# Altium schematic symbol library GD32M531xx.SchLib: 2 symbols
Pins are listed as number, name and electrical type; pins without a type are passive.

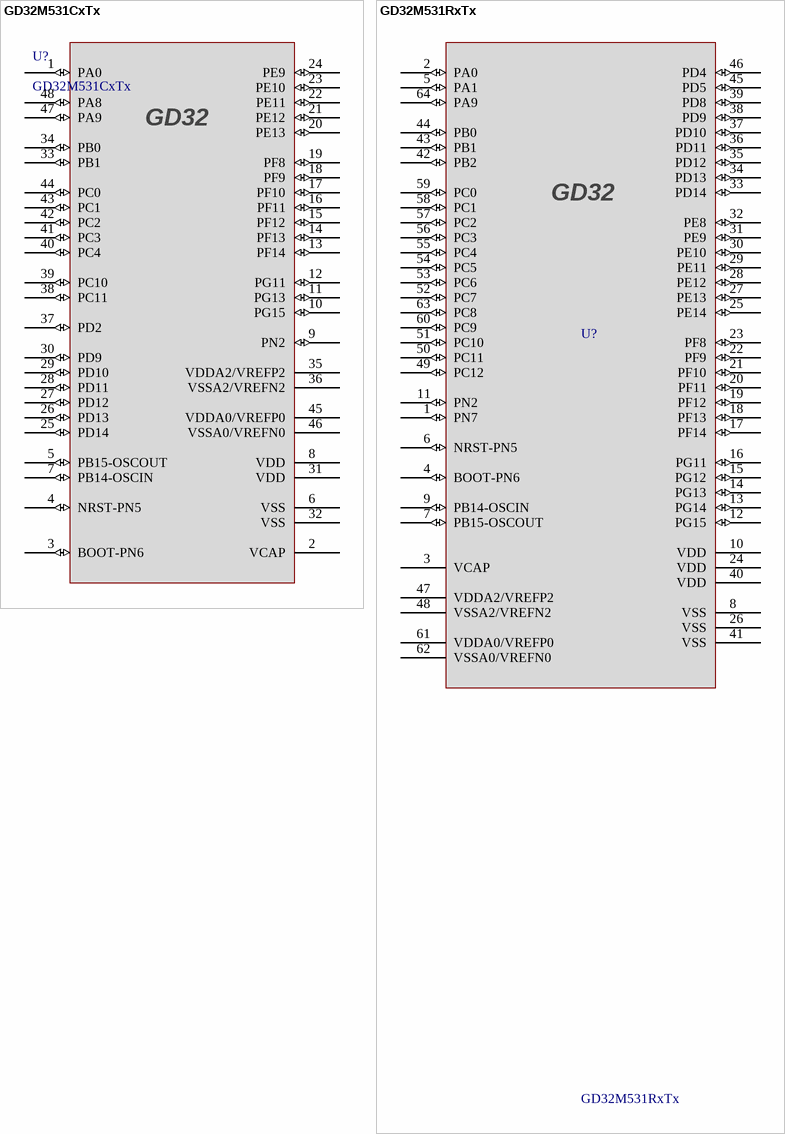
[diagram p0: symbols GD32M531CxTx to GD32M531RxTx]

## GD32M531CxTx
designator U?
footprint LQFP48_7x7x1.6
pins: 1 PA0 (io), 2 VCAP (power), 3 BOOT-PN6 (io), 4 NRST-PN5 (io), 5 PB15-OSCOUT (io), 6 VSS (power), 7 PB14-OSCIN (io), 8 VDD (power), 9 PN2 (io), 10 PG15 (io), 11 PG13 (io), 12 PG11 (io), 13 PF14 (io), 14 PF13 (io), 15 PF12 (io), 16 PF11 (io), 17 PF10 (io), 18 PF9 (io), 19 PF8 (io), 20 PE13 (io), 21 PE12 (io), 22 PE11 (io), 23 PE10 (io), 24 PE9 (io), 25 PD14 (io), 26 PD13 (io), 27 PD12 (io), 28 PD11 (io), 29 PD10 (io), 30 PD9 (io), 31 VDD (power), 32 VSS (power), 33 PB1 (io), 34 PB0 (io), 35 VDDA2/VREFP2 (power), 36 VSSA2/VREFN2 (power), 37 PD2 (io), 38 PC11 (io), 39 PC10 (io), 40 PC4 (io), 41 PC3 (io), 42 PC2 (io), 43 PC1 (io), 44 PC0 (io), 45 VDDA0/VREFP0 (power), 46 VSSA0/VREFN0 (power), 47 PA9 (io), 48 PA8 (io)

## GD32M531RxTx
designator U?
footprint LQPF64_10x10x1.6
pins: 1 PN7 (io), 2 PA0 (io), 3 VCAP (power), 4 BOOT-PN6 (io), 5 PA1 (io), 6 NRST-PN5 (io), 7 PB15-OSCOUT (io), 8 VSS (power), 9 PB14-OSCIN (io), 10 VDD (power), 11 PN2 (io), 12 PG15 (io), 13 PG14 (io), 14 PG13 (io), 15 PG12 (io), 16 PG11 (io), 17 PF14 (io), 18 PF13 (io), 19 PF12 (io), 20 PF11 (io), 21 PF10 (io), 22 PF9 (io), 23 PF8 (io), 24 VDD (power), 25 PE14 (io), 26 VSS (power), 27 PE13 (io), 28 PE12 (io), 29 PE11 (io), 30 PE10 (io), 31 PE9 (io), 32 PE8 (io), 33 PD14 (io), 34 PD13 (io), 35 PD12 (io), 36 PD11 (io), 37 PD10 (io), 38 PD9 (io), 39 PD8 (io), 40 VDD (power), 41 VSS (power), 42 PB2 (io), 43 PB1 (io), 44 PB0 (io), 45 PD5 (io), 46 PD4 (io), 47 VDDA2/VREFP2 (power), 48 VSSA2/VREFN2 (power), 49 PC12 (io), 50 PC11 (io), 51 PC10 (io), 52 PC7 (io), 53 PC6 (io), 54 PC5 (io), 55 PC4 (io), 56 PC3 (io), 57 PC2 (io), 58 PC1 (io), 59 PC0 (io), 60 PC9 (io), 61 VDDA0/VREFP0 (power), 62 VSSA0/VREFN0 (power), 63 PC8 (io), 64 PA9 (io)
2 alternate drawings of the same symbol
